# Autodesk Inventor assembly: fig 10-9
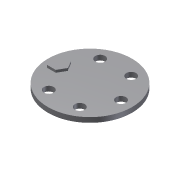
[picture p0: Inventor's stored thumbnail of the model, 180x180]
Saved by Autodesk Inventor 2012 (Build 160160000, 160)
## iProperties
Created: 2008-05
Part Number: fig 10-9
Document SubType Name: Assembly
Designer: CADCIM
Author: CADCIM
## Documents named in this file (3)
- C:\Users\CadCim\Documents\SAILESH\inventor-2011-fact-prt\c10-inv-2011-prt\c10_inv_2012_prt\fig 10-9.iam
- C:\Users\CadCim\Documents\SAILESH\inventor-2011-fact-prt\c10-inv-2011-prt\c10_inv_2012_prt\Part4.ipt
- C:\Users\CadCim\Documents\SAILESH\inventor-2011-fact-prt\c10-inv-2011-prt\c10_inv_2012_prt\Part5.ipt
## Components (2 placed, 2 different names)
1. Part4:1
2. Part5:1
